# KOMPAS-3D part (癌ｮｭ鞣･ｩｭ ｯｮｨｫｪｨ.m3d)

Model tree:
1. Эскиз:1
2. Операция выдавливания:1
     Расстояние 1 = 5
3. Эскиз:2
4. Операция выдавливания:2
     Расстояние 1 = 12
5. Эскиз:3
6. Операция выдавливания:3
     Расстояние 1 = 30
7. Эскиз:4
8. Операция выдавливания:4
     Расстояние 1 = 12
9. Скругление:1
     Радиус = 15
10. Скругление:2
     Радиус = 10
11. Скругление:3
     Радиус = 10
12. Скругление:4
     Радиус = 7
13. Скругление:5
     Радиус = 2
14. Скругление:6
     Радиус = 2
15. Скругление:7
     Радиус = 1
16. Скругление:8
     Радиус = 1
17. Скругление:9
     Радиус = 1
18. Эскиз:5
19. Вырезать элемент выдавливания:1
     Расстояние 2 = 30
20. Фаска:1
     Угол = 45; Длина 1 = 1.5; Длина 2 = 1.5
21. Фаска:2
     Угол = 45; Длина 1 = 1.5; Длина 2 = 1.5
22. Эскиз:6
23. Вырезать элемент выдавливания:2
     Расстояние 2 = 30; Расстояние 1 = 30
24. Эскиз:7
25. Вырезать элемент выдавливания:3
     Расстояние 1 = 12
26. Скругление:10
     Радиус = 1
27. Скругление:11
     Радиус = 1
28. Скругление:12
     Радиус = 1
29. Скругление:15
     Радиус = 1
30. Скругление:17
     Радиус = 1
31. Скругление:18
     Радиус = 1
32. Скругление:19
     Радиус = 0.7
33. Скругление:20
     Радиус = 2
34. Скругление:21
     Радиус = 2
35. Эскиз:8
36. Вырезать элемент выдавливания:4
     Расстояние 2 = 30; Расстояние 1 = 30
37. Фаска:3
     Угол = 45; Длина 1 = 1; Длина 2 = 1
38. Скругление:22
     Радиус = 1
39. Скругление:23
     Радиус = 1
40. Скругление:24
     Радиус = 1
